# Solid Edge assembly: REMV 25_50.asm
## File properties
Title: Zylinder
Author: ahadarics
Template: iso metric assembly.asm
Last saved by: ahadarics
Revision: 5
Application: Solid Edge
Username: ahadarics
Dokumentum tartalom típus: 1
Document Number: REMV 25/50
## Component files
Profilrohr.par
Kolbenstange.par
Kit_1.par
Kit_2.par
Mutter_1.par
Mutter_2.par
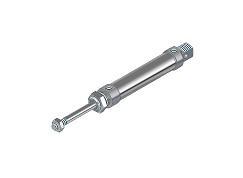
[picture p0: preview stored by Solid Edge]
